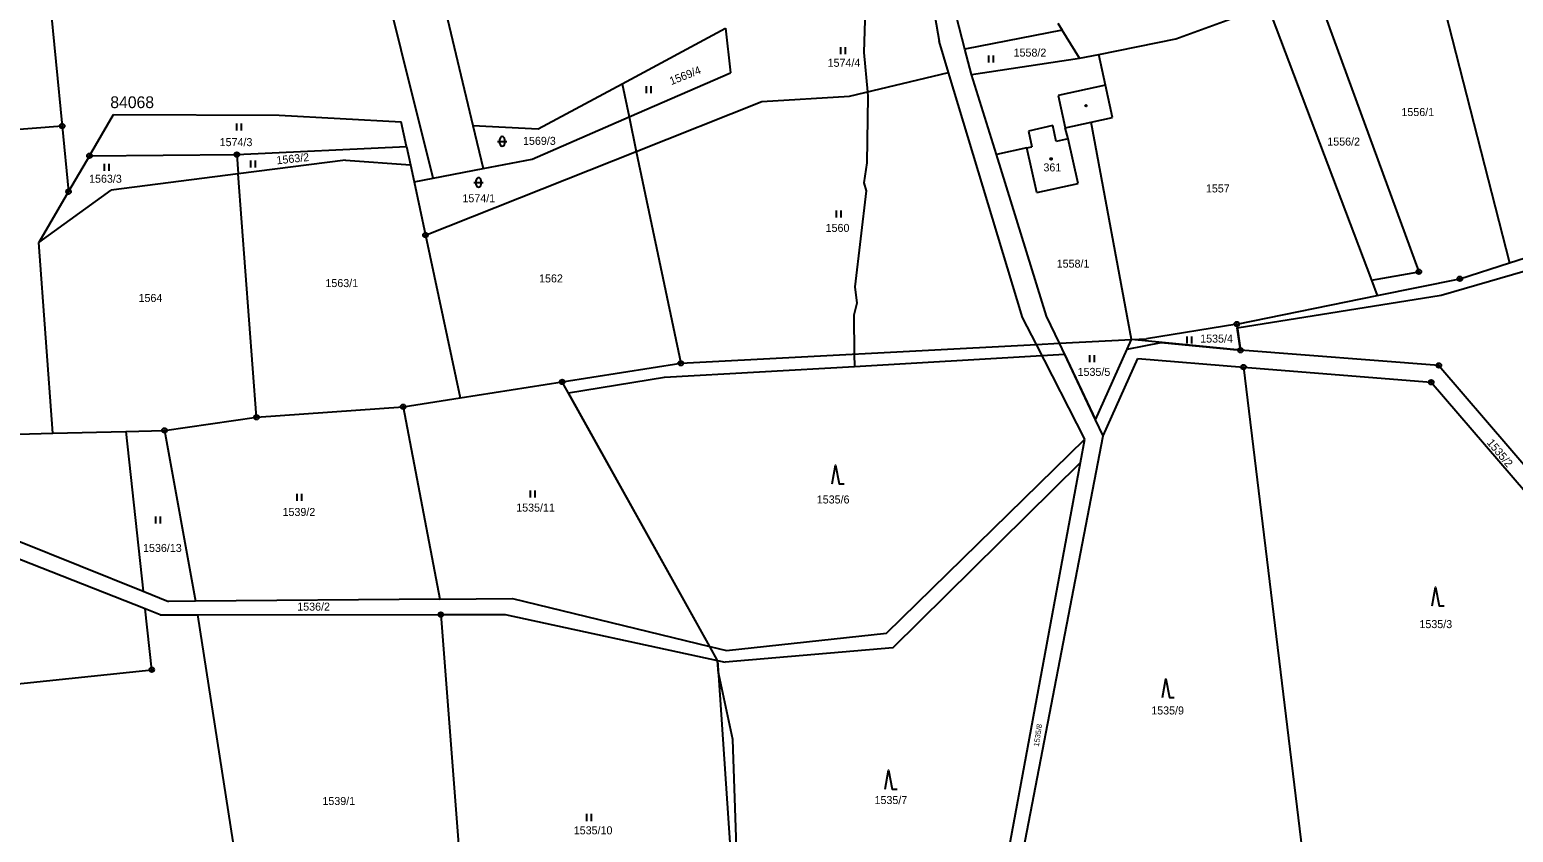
# Model space of a CAD drawing. Extents: x -445050 to -440454, y -1134563 to -1129741.
# Drawn here: x -442830.3 to -442515, y -1132475.8 to -1132305.3 of the extents above; entities that cross this region are included whole.
import ezdxf

# ---------------------------------------------------------------- set-up
doc = ezdxf.new("R2010")
doc.units = 0
for name, color, linetype in [('Vrstva 1', 7, 'Continuous'), ('Vrstva 18', 7, 'Continuous'), ('Vrstva 19', 7, 'Continuous'), ('Vrstva 24', 7, 'Continuous'), ('Vrstva 25', 7, 'Continuous'), ('Vrstva 3', 7, 'Continuous'), ('Vrstva 37', 7, 'Continuous'), ('Vrstva 4', 7, 'Continuous'), ('Vrstva 52', 7, 'Continuous'), ('Vrstva 53', 7, 'Continuous')]:
    doc.layers.add(name, color=color, linetype=linetype)

msp = doc.modelspace()

# ---------------------------------------------------------------- linework, layer by layer
at = {"layer": 'Vrstva 1'}
for points in [[(-442744.55, -1132336.84), (-442764.9, -1132254.99)], [(-442753.42, -1132252.82), (-442736.08, -1132325.65)], [(-442828.71, -1132270.81), (-442823.35, -1132325.77)], [(-442532.53, -1132289.48), (-442515.83, -1132354.84)], [(-442556.18, -1132299.07), (-442535.07, -1132356.7)], [(-442637.94, -1132302.45), (-442637.03, -1132307.74)], [(-442631.54, -1132309.43), (-442633.31, -1132302.59)], [(-442586.72, -1132307.27), (-442567.21, -1132300.16)], [(-442567.21, -1132300.16), (-442545.15, -1132358.52)], [(-442704.37, -1132316.78), (-442682.38, -1132304.97)], [(-442682.38, -1132304.97), (-442681.31, -1132314.46)], [(-442610.85, -1132305.38), (-442631.54, -1132309.43)], [(-442611.76, -1132303.88), (-442610.85, -1132305.38)], [(-442607.21, -1132311.36), (-442610.85, -1132305.38)], [(-442635.02, -1132314.39), (-442637.03, -1132307.74)], [(-442603.1, -1132310.54), (-442586.72, -1132307.27)], [(-442630.14, -1132314.81), (-442631.54, -1132309.43)], [(-442630.14, -1132314.81), (-442607.21, -1132311.36)], [(-442607.21, -1132311.36), (-442603.1, -1132310.54)], [(-442601.66, -1132317.1), (-442603.1, -1132310.54)], [(-442702.89, -1132323.83), (-442681.31, -1132314.46)], [(-442656.06, -1132319.45), (-442635.02, -1132314.39)], [(-442619.29, -1132366.41), (-442635.02, -1132314.39)], [(-442624.84, -1132331.84), (-442630.14, -1132314.81)], [(-442722.23, -1132326.38), (-442704.37, -1132316.78)], [(-442704.37, -1132316.78), (-442702.89, -1132323.83)], [(-442600.16, -1132323.94), (-442601.66, -1132317.1)], [(-442701.36, -1132331.14), (-442674.7, -1132320.56)], [(-442674.7, -1132320.56), (-442656.06, -1132319.45)], [(-442817.55, -1132332.08), (-442812.44, -1132323.33)], [(-442812.44, -1132323.33), (-442777.27, -1132323.47)], [(-442777.27, -1132323.47), (-442751.3, -1132324.84)], [(-442723.51, -1132332.78), (-442702.89, -1132323.83)], [(-442702.89, -1132323.83), (-442701.36, -1132331.14)], [(-442604.7, -1132324.93), (-442600.16, -1132323.94)], [(-442823.35, -1132325.77), (-442846.18, -1132327.55)], [(-442823.35, -1132325.77), (-442822, -1132339.7)], [(-442750.18, -1132330.09), (-442751.3, -1132324.84)], [(-442736.08, -1132325.65), (-442722.23, -1132326.38)], [(-442736.08, -1132325.65), (-442733.9, -1132334.78)], [(-442610.22, -1132326.15), (-442604.7, -1132324.93)], [(-442609.6, -1132328.48), (-442610.22, -1132326.15)], [(-442596.16, -1132371.1), (-442604.7, -1132324.93)], [(-442786.24, -1132331.82), (-442750.18, -1132330.09)], [(-442750.18, -1132330.09), (-442749.35, -1132333.97)], [(-442618.4, -1132330.4), (-442624.84, -1132331.84)], [(-442616.26, -1132339.91), (-442618.4, -1132330.4)], [(-442607.48, -1132337.94), (-442609.6, -1132328.48)], [(-442817.55, -1132332.08), (-442822, -1132339.7)], [(-442817.55, -1132332.08), (-442786.24, -1132331.82)], [(-442786.24, -1132331.82), (-442785.93, -1132335.92)], [(-442763.18, -1132333.02), (-442785.93, -1132335.92)], [(-442763.18, -1132333.02), (-442749.35, -1132333.97)], [(-442749.35, -1132333.97), (-442748.57, -1132337.62)], [(-442746.16, -1132348.93), (-442701.36, -1132331.14)], [(-442733.9, -1132334.78), (-442723.51, -1132332.78)], [(-442701.36, -1132331.14), (-442691.93, -1132376.15)], [(-442614.17, -1132366.14), (-442624.84, -1132331.84)], [(-442785.93, -1132335.92), (-442812.95, -1132339.36)], [(-442782.04, -1132387.61), (-442785.93, -1132335.92)], [(-442748.57, -1132337.62), (-442744.55, -1132336.84)], [(-442744.55, -1132336.84), (-442733.9, -1132334.78)], [(-442828.3, -1132350.49), (-442812.95, -1132339.36)], [(-442822, -1132339.7), (-442828.3, -1132350.49)], [(-442748.57, -1132337.62), (-442746.16, -1132348.93)], [(-442616.26, -1132339.91), (-442607.48, -1132337.94)], [(-442515.83, -1132354.84), (-442484.29, -1132344.75)], [(-442746.16, -1132348.93), (-442738.79, -1132383.5)], [(-442825.34, -1132391.01), (-442828.3, -1132350.49)], [(-442526.36, -1132358.21), (-442515.83, -1132354.84)], [(-442545.15, -1132358.52), (-442535.07, -1132356.7)], [(-442545.15, -1132358.52), (-442543.93, -1132361.77)], [(-442543.93, -1132361.77), (-442526.36, -1132358.21)], [(-442573.78, -1132367.82), (-442543.93, -1132361.77)], [(-442616.35, -1132372.16), (-442619.29, -1132366.41)], [(-442611.45, -1132371.9), (-442614.17, -1132366.14)], [(-442573.78, -1132367.82), (-442592.94, -1132370.93)], [(-442573.78, -1132367.82), (-442572.97, -1132373.39)], [(-442616.35, -1132372.16), (-442611.45, -1132371.9)], [(-442611.45, -1132371.9), (-442596.16, -1132371.1)], [(-442603.76, -1132388.16), (-442611.45, -1132371.9)], [(-442603.76, -1132388.16), (-442596.16, -1132371.1)], [(-442596.16, -1132371.1), (-442592.94, -1132370.93)], [(-442572.97, -1132373.39), (-442596.16, -1132371.1)], [(-442691.93, -1132376.15), (-442616.35, -1132372.16)], [(-442606.07, -1132392.3), (-442616.35, -1132372.16)], [(-442602.15, -1132391.56), (-442594.82, -1132375.13)], [(-442594.82, -1132375.13), (-442572.33, -1132376.95)], [(-442530.82, -1132376.6), (-442572.97, -1132373.39)], [(-442717.09, -1132380.1), (-442691.93, -1132376.15)], [(-442572.33, -1132376.95), (-442557.53, -1132498.98)], [(-442572.33, -1132376.95), (-442532.45, -1132380.18)], [(-442530.82, -1132376.6), (-442500.64, -1132411.71)], [(-442738.79, -1132383.5), (-442717.09, -1132380.1)], [(-442685.74, -1132436.3), (-442717.09, -1132380.1)], [(-442532.45, -1132380.18), (-442503.69, -1132413.58)], [(-442750.9, -1132385.4), (-442738.79, -1132383.5)], [(-442801.63, -1132390.42), (-442782.04, -1132387.61)], [(-442782.04, -1132387.61), (-442750.9, -1132385.4)], [(-442750.9, -1132385.4), (-442743.14, -1132426.22)], [(-442832.76, -1132391.19), (-442825.34, -1132391.01)], [(-442825.34, -1132391.01), (-442809.81, -1132390.62)], [(-442809.81, -1132390.62), (-442801.63, -1132390.42)], [(-442809.81, -1132390.62), (-442806.13, -1132424.56)], [(-442801.63, -1132390.42), (-442795.03, -1132426.67)], [(-442602.15, -1132391.56), (-442603.76, -1132388.16)], [(-442648.22, -1132433.44), (-442606.07, -1132392.3)], [(-442621.64, -1132492.67), (-442602.15, -1132391.56)], [(-442606.98, -1132397.21), (-442606.07, -1132392.3)], [(-442646.87, -1132436.61), (-442606.98, -1132397.21)], [(-442624.13, -1132489.82), (-442606.98, -1132397.21)], [(-442832.92, -1132413.76), (-442806.13, -1132424.56)], [(-442805.72, -1132428.34), (-442834.32, -1132417.03)], [(-442806.13, -1132424.56), (-442800.79, -1132426.72)], [(-442804.33, -1132441.24), (-442805.72, -1132428.34)], [(-442802.52, -1132429.61), (-442805.72, -1132428.34)], [(-442795.03, -1132426.67), (-442800.79, -1132426.72)], [(-442743.14, -1132426.22), (-442795.03, -1132426.67)], [(-442743.14, -1132426.22), (-442727.7, -1132426.09)], [(-442727.7, -1132426.09), (-442685.74, -1132436.3)], [(-442802.52, -1132429.61), (-442794.57, -1132429.6)], [(-442794.57, -1132429.6), (-442742.88, -1132429.54)], [(-442794.57, -1132429.6), (-442781.57, -1132513.28)], [(-442742.88, -1132429.54), (-442729.2, -1132429.53)], [(-442742.88, -1132429.54), (-442736.74, -1132509.57)], [(-442729.2, -1132429.53), (-442684.09, -1132439.27)], [(-442682.19, -1132437.17), (-442648.22, -1132433.44)], [(-442685.74, -1132436.3), (-442682.19, -1132437.17)], [(-442646.87, -1132436.61), (-442682.46, -1132439.62)], [(-442862.01, -1132447.26), (-442804.33, -1132441.24)], [(-442684.09, -1132439.27), (-442682.46, -1132439.62)], [(-442684.09, -1132439.27), (-442679.3, -1132510.41)]]:
    msp.add_lwpolyline(points, dxfattribs=at)
at = {"layer": 'Vrstva 24'}
for centre, radius in [((-442823.35, -1132325.77), 0.5), ((-442823.35, -1132325.77), 0.1), ((-442817.55, -1132332.08), 0.5), ((-442817.55, -1132332.08), 0.1), ((-442786.24, -1132331.82), 0.5), ((-442786.24, -1132331.82), 0.1), ((-442822, -1132339.7), 0.5), ((-442822, -1132339.7), 0.1), ((-442746.16, -1132348.93), 0.5), ((-442746.16, -1132348.93), 0.1), ((-442535.07, -1132356.7), 0.5), ((-442535.07, -1132356.7), 0.1), ((-442526.36, -1132358.21), 0.5), ((-442526.36, -1132358.21), 0.1), ((-442573.78, -1132367.82), 0.5), ((-442573.78, -1132367.82), 0.1), ((-442572.97, -1132373.39), 0.5), ((-442572.97, -1132373.39), 0.1), ((-442691.93, -1132376.15), 0.5), ((-442691.93, -1132376.15), 0.1), ((-442572.33, -1132376.95), 0.5), ((-442572.33, -1132376.95), 0.1), ((-442530.82, -1132376.6), 0.5), ((-442530.82, -1132376.6), 0.1), ((-442717.09, -1132380.1), 0.5), ((-442717.09, -1132380.1), 0.1), ((-442532.45, -1132380.18), 0.5), ((-442532.45, -1132380.18), 0.1), ((-442782.04, -1132387.61), 0.5), ((-442782.04, -1132387.61), 0.1), ((-442750.9, -1132385.4), 0.5), ((-442750.9, -1132385.4), 0.1), ((-442801.63, -1132390.42), 0.5), ((-442801.63, -1132390.42), 0.1), ((-442742.88, -1132429.54), 0.5), ((-442742.88, -1132429.54), 0.1), ((-442804.33, -1132441.24), 0.5), ((-442804.33, -1132441.24), 0.1)]:
    msp.add_circle(centre, radius, dxfattribs=at)
at = {"layer": 'Vrstva 25'}
for p, q in [((-442657.89, -1132310.53), (-442657.89, -1132309.03)), ((-442656.89, -1132310.53), (-442656.89, -1132309.03)), ((-442626.48, -1132312.3), (-442626.48, -1132310.8)), ((-442625.48, -1132312.3), (-442625.48, -1132310.8)), ((-442699.19, -1132318.79), (-442699.19, -1132317.29)), ((-442698.19, -1132318.79), (-442698.19, -1132317.29)), ((-442786.26, -1132326.74), (-442786.26, -1132325.24)), ((-442785.26, -1132326.74), (-442785.26, -1132325.24)), ((-442730.85, -1132329.02), (-442728.85, -1132329.02)), ((-442730.35, -1132329.52), (-442730.35, -1132328.52)), ((-442729.35, -1132328.52), (-442729.35, -1132329.52)), ((-442814.34, -1132335.28), (-442814.34, -1132333.78)), ((-442813.34, -1132335.28), (-442813.34, -1132333.78)), ((-442783.29, -1132334.58), (-442783.29, -1132333.08)), ((-442782.29, -1132334.58), (-442782.29, -1132333.08)), ((-442735.37, -1132338.24), (-442735.37, -1132337.24)), ((-442734.37, -1132337.24), (-442734.37, -1132338.24)), ((-442735.87, -1132337.74), (-442733.87, -1132337.74)), ((-442658.81, -1132345.22), (-442658.81, -1132343.72)), ((-442657.81, -1132345.22), (-442657.81, -1132343.72)), ((-442584.33, -1132371.95), (-442584.33, -1132370.45)), ((-442583.33, -1132371.95), (-442583.33, -1132370.45)), ((-442604.99, -1132375.92), (-442604.99, -1132374.42)), ((-442603.99, -1132375.92), (-442603.99, -1132374.42)), ((-442723.82, -1132404.64), (-442723.82, -1132403.14)), ((-442722.82, -1132404.64), (-442722.82, -1132403.14)), ((-442773.44, -1132405.35), (-442773.44, -1132403.85)), ((-442772.44, -1132405.35), (-442772.44, -1132403.85)), ((-442803.45, -1132410.19), (-442803.45, -1132408.69)), ((-442802.45, -1132410.19), (-442802.45, -1132408.69)), ((-442711.87, -1132473.37), (-442711.87, -1132471.87)), ((-442710.87, -1132473.37), (-442710.87, -1132471.87))]:
    msp.add_line(p, q, dxfattribs=at)
for points in [[(-442659.72, -1132401.79), (-442659.02, -1132397.79), (-442658.22, -1132401.79), (-442657.22, -1132401.79)], [(-442532.23, -1132427.7), (-442531.53, -1132423.7), (-442530.73, -1132427.7), (-442529.73, -1132427.7)], [(-442589.57, -1132447.15), (-442588.87, -1132443.15), (-442588.07, -1132447.15), (-442587.07, -1132447.15)], [(-442648.46, -1132466.6), (-442647.76, -1132462.6), (-442646.96, -1132466.6), (-442645.96, -1132466.6)]]:
    msp.add_lwpolyline(points, dxfattribs=at)
for centre in [(-442605.79, -1132321.43), (-442613.21, -1132332.74)]:
    msp.add_circle(centre, 0.175, dxfattribs=at)
for centre, start, end in [((-442729.85, -1132328.52), 0, 180), ((-442729.85, -1132329.52), 180, 0), ((-442734.87, -1132337.24), 0, 180), ((-442734.87, -1132338.24), 180, 0)]:
    msp.add_arc(centre, 0.5, start, end, dxfattribs=at)
at = {"layer": 'Vrstva 3'}
for points in [[(-442612.88, -1132325.67), (-442618.04, -1132326.83)], [(-442618.04, -1132326.83), (-442617.29, -1132330.15)], [(-442612.12, -1132329.04), (-442612.88, -1132325.67)], [(-442618.4, -1132330.4), (-442617.29, -1132330.15)], [(-442616.26, -1132339.91), (-442618.4, -1132330.4)], [(-442609.6, -1132328.48), (-442612.12, -1132329.04)], [(-442607.48, -1132337.94), (-442609.6, -1132328.48)], [(-442616.26, -1132339.91), (-442607.48, -1132337.94)]]:
    msp.add_lwpolyline(points, dxfattribs=at)
at = {"layer": 'Vrstva 37'}
msp.add_circle((-442613.21, -1132332.74), 0.175, dxfattribs=at)
at = {"layer": 'Vrstva 4'}
for points in [[(-442601.66, -1132317.1), (-442611.72, -1132319.31)], [(-442611.72, -1132319.31), (-442610.22, -1132326.15)], [(-442612.88, -1132325.67), (-442618.04, -1132326.83)], [(-442618.04, -1132326.83), (-442617.29, -1132330.15)], [(-442612.12, -1132329.04), (-442612.88, -1132325.67)], [(-442618.4, -1132330.4), (-442617.29, -1132330.15)], [(-442609.6, -1132328.48), (-442612.12, -1132329.04)]]:
    msp.add_lwpolyline(points, dxfattribs=at)
at = {"layer": 'Vrstva 52'}
for points in [[(-442652.78, -1132303.29), (-442652.98, -1132310.13), (-442652.22, -1132318.53), (-442652.13, -1132319.5), (-442652.34, -1132333.55), (-442652.98, -1132337.81), (-442652.55, -1132339.51), (-442654.89, -1132359.94), (-442654.47, -1132363.35), (-442655.11, -1132365.9), (-442655.05, -1132374.2), (-442655.03, -1132376.85)], [(-442655.03, -1132376.85), (-442615.16, -1132374.5), (-442610.35, -1132374.22), (-442603.76, -1132388.16), (-442597.06, -1132373.13), (-442589.82, -1132371.73), (-442572.97, -1132373.39), (-442573.66, -1132368.62), (-442530.37, -1132361.65), (-442500, -1132352.91), (-442480.46, -1132345.93), (-442479.18, -1132345.49), (-442467.93, -1132376.96), (-442450.5, -1132420.95), (-442439.34, -1132450.86), (-442437.46, -1132455.89), (-442429.98, -1132475.95)], [(-442679.3, -1132510.41), (-442680.06, -1132499.18), (-442679.61, -1132491.35), (-442680.87, -1132456.05), (-442683.81, -1132442.18), (-442683.9, -1132442.07), (-442684.09, -1132439.27), (-442685.74, -1132436.3), (-442715.8, -1132382.41), (-442695.34, -1132379.1), (-442655.03, -1132376.85)]]:
    msp.add_lwpolyline(points, dxfattribs=at)

# ---------------------------------------------------------------- texts
at = {"layer": 'Vrstva 18'}
for s, p in [('1574/4', (-442660.71, -1132313.18)), ('1558/2', (-442621.19, -1132311.02)), ('1556/1', (-442538.78, -1132323.64)), ('1569/3', (-442725.43, -1132329.76)), ('1574/3', (-442789.89, -1132330.03)), ('1556/2', (-442554.53, -1132329.92)), ('1563/3', (-442817.64, -1132337.81)), ('1574/1', (-442738.31, -1132341.96)), ('1557', (-442580.33, -1132339.87)), ('1560', (-442661.13, -1132348.25)), ('1558/1', (-442612.03, -1132355.84)), ('1563/1', (-442767.42, -1132359.97)), ('1562', (-442722.02, -1132358.98)), ('1564', (-442807.13, -1132363.13)), ('1535/4', (-442581.54, -1132371.76)), ('1535/5', (-442607.59, -1132378.83)), ('1539/2', (-442776.53, -1132408.58)), ('1535/11', (-442726.88, -1132407.66)), ('1535/6', (-442663.01, -1132405.93)), ('1536/13', (-442806.17, -1132416.22)), ('1536/2', (-442773.41, -1132428.69)), ('1535/3', (-442534.95, -1132432.4)), ('1535/9', (-442591.94, -1132450.74)), ('1539/1', (-442768.06, -1132469.97)), ('1535/7', (-442650.74, -1132469.77)), ('1535/10', (-442714.65, -1132476.2))]:
    msp.add_text(s, height=1.7, dxfattribs=at).set_placement(p)
for s, height, rotation, p in [('1569/4', 1.7, 21.5919, (-442693.91, -1132317.09)), ('1563/2', 1.7, 6.0237, (-442777.73, -1132333.91)), ('1535/2', 1.7, 310.1013, (-442520.73, -1132393.08)), ('1535/8', 1.14, 81.3666, (-442615.83, -1132457.61))]:
    msp.add_text(s, height=height, rotation=rotation, dxfattribs=at).set_placement(p)
at = {"layer": 'Vrstva 19'}
msp.add_text('361', height=1.7, dxfattribs=at).set_placement((-442614.85, -1132335.4))
at = {"layer": 'Vrstva 53'}
msp.add_text('84068', height=2.5, dxfattribs=at).set_placement((-442813.13, -1132321.96))

doc.saveas('drawing.dxf')
